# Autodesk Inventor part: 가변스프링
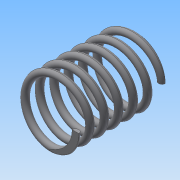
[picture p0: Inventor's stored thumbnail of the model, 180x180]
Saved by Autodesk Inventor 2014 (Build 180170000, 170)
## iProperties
Created: 2019-07
Part Number: 가변스프링
Material: 일반
Document SubType Name: Modeling
Designer: net
Density: 1 g/cm^3
Appearance: 기본값
Mass: 0.990081 g
Surface Area: 20.0894 cm^2
Volume: 0.990081 cm^3
Author: net
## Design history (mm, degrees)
sketch "스케치1"
  geometry: L1 (0, 0)-(8.5, 0); L2 (8.5, 0)-(8.5, 25.33); L3 (8.5, 25.33)-(0, 25.33); L4 (0, 25.33)-(0, 0); C1 r 1 at (8.5, 0)
  constraints: 8 end point, 2 parallel, 1 centre point, 1 coincident, 1 horizontal, 1 perpendicular
  dimensions: "d0" = 17 diameter of L2 L4; "d1" = 25.33013 distance of L1.end L2.end (derived); "d2" = 2 diameter of C1
feature "코일1" pitch "d3" = 10; turns "d5" = 6; dims "d4" = 25.33013 (= d1), "d6" = 0, angle "d7" = 90 deg, angle "d8" = 90 deg, "d9" = 0, "d10" = 0
node "작업 평면1"
node "작업 평면2"
sketch "스케치2"
  geometry: L1 (-1, 0)-(1, 0) reference; 1 further point
  constraints: 1 horizontal alignment
extrude "돌출1" cut sketch "스케치2" stored distance "d13" = 10; taper "d14" = 0 deg
sketch "스케치3"
  geometry: L1 (7.5, 0)-(9.5, 0) reference; 1 further point
  constraints: 1 horizontal alignment
extrude "돌출2" cut sketch "스케치3" stored distance "d15" = 10; taper "d16" = 0 deg
node "솔리드1"
node "절단 모서리 투영1"
node "절단 모서리 투영2"
other parameters: "d11" = 90 deg, "d12" = 90 deg
